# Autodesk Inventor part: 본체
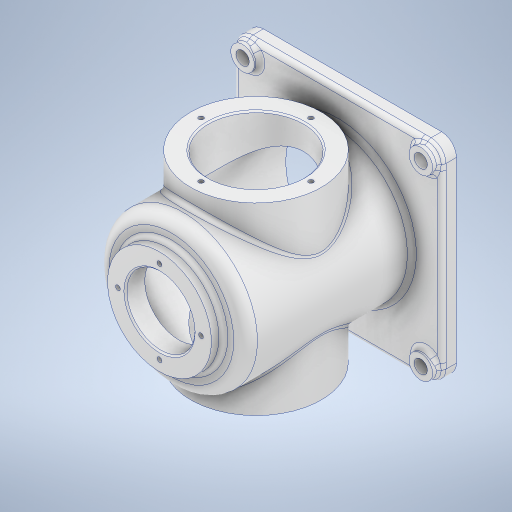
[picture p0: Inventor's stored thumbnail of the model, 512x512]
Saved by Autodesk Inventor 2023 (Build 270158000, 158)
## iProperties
Created: 2025-05
Part Number: 본체
Material: 알루미늄 6061
Document SubType Name: Modeling
Designer: user
Density: 2.7 g/cm^3
Appearance: 알루미늄 - 평지
Mass: 1130.9 g
Surface Area: 1201.4 cm^2
Volume: 418.852 cm^3
Author: user
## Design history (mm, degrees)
sketch "스케치3"
  geometry: C1 r 50 at (0, 0); 1 further point
  constraints: 1 centre point, 1 coincident
  dimensions: "d0" = 100 diameter of C1
extrude "돌출1" new body sketch "스케치3" distance "d1" = 122; taper "d2" = 0 deg
sketch "스케치9"
  geometry: L1 (-70, -70)-(70, -70); L2 (70, -70)-(70, 70); L3 (70, 70)-(-70, 70); L4 (-70, 70)-(-70, -70); L5 (-70, -70)-(70, 70); L6 (70, -70)-(-70, 70); 1 further point
  constraints: 12 end point, 2 midpoint, 2 parallel, 1 horizontal, 1 perpendicular
  dimensions: "d12" = 140 distance of L3.end L2.end; "d13" = 140 distance of L2.end L1.end
extrude "돌출4" join sketch "스케치9" distance "d14" = 10; taper "d15" = 0 deg
sketch "스케치12"
  geometry: L1 (-72.836, 65)-(75.341, 65); L2 (-70, 0)-(70, 0) reference; L3 (0, -24.4)-(0, 146.4) reference; C1 r 44 at (0, 65); 1 further point
  constraints: 2 end point, 2 point on line, 1 centre point, 1 horizontal
  dimensions: "d19" = 65 distance between parallel lines of L2 L1; "d20" = 88 diameter of C1
extrude "돌출6" join sketch "스케치12" stored distance "d21" = 124; taper "d22" = 0 deg
sketch "스케치10"
  geometry: C1 r 45 at (0, 0); 1 further point
  constraints: 1 centre point, 1 coincident
  dimensions: "d16" = 90 diameter of C1
extrude "돌출5" cut sketch "스케치10" distance "d17" = 117; taper "d18" = 0 deg
sketch "스케치13"
  geometry: L1 (0, 89.4)-(0, -81.4) reference; L2 (64.744, 0)-(-80.929, 0); L3 (-70, 65)-(70, 65) reference; C1 r 32 at (0, 0); 1 further point
  constraints: 2 end point, 2 point on line, 1 centre point, 1 horizontal
  dimensions: "d23" = 64 diameter of C1; "d24" = 65 distance between parallel lines of L3 L2
extrude "돌출7" cut sketch "스케치13" extent not by distance; stored distance "d25" = 0; taper "d26" = 0 deg
sketch "스케치15"
  geometry: C1 r 35 at (0, 0); 1 further point
  constraints: 1 centre point, 1 coincident
  dimensions: "d27" = 70 diameter of C1
extrude "돌출8" join sketch "스케치15" distance "d28" = 8; taper "d29" = 0 deg
sketch "스케치16"
  geometry: C1 r 23 at (0, 0); 1 further point
  constraints: 1 centre point, 1 coincident
  dimensions: "d30" = 46 diameter of C1
extrude "돌출9" cut sketch "스케치16" extent not by distance; stored distance "d31" = 0; taper "d32" = 0 deg
sketch "스케치17"
  geometry: L1 (-98, 0)-(98, 0) reference; L2 (0, -98)-(0, 98) reference; 2 further points
  constraints: 1 point on line
  dimensions: "d34" = 56 diameter of point (-28, 0) L2
hole "구멍1" sketch "스케치17" at (-28, 0) diameter "d35" = 3.242; stored, may be unused: countersink angle "d39" = 90 deg, drill point angle "d41" = 118 deg; dims "d36" = 8, "d37" = 4, "d38" = 2, "d40" = 10
sketch "스케치18"
  geometry: L1 (0, -91)-(0, 91) reference; L2 (-79.6, 0)-(91.263, 0); L3 (70, -65)-(-70, -65) reference; 2 further points
  constraints: 2 end point, 1 horizontal, 1 point on line
  dimensions: "d45" = 65 distance between parallel lines of L3 L2; "d46" = 74 diameter of point (0, 37) L2
hole "구멍2" sketch "스케치18" at (0, 37) diameter "d47" = 3.242; stored, may be unused: countersink angle "d51" = 90 deg, drill point angle "d53" = 118 deg; dims "d48" = 8, "d49" = 4, "d50" = 2, "d52" = 10
fillet "모깎기1" dims "d57" = 10
sketch "스케치19"
  geometry: C1 r 8 at (60, 60); C2 r 8 at (60, -60); C3 r 8 at (-60, 60); C4 r 8 at (-60, -60); A1 r 10 centre (60, 60) between (70, 60) and (60, 70) reference; A2 r 10 centre (60, -60) between (60, -70) and (70, -60) reference; A3 r 10 centre (-60, 60) between (-60, 70) and (-70, 60) reference; A4 r 10 centre (-60, -60) between (-70, -60) and (-60, -70) reference; 1 further point
  constraints: 4 centre point, 4 coincident
  dimensions: "d58" = 16 diameter of C1; "d59" = 16 diameter of C2; "d60" = 16 diameter of C3; "d61" = 16 diameter of C4
extrude "돌출10" join sketch "스케치19" distance "d62" = 4; taper "d63" = 0 deg
sketch "스케치20"
  geometry: 1 further point
sketch "스케치21"
  geometry: C1 r 8 at (0, -120) reference; C2 r 4.5 at (0, -120); C3 r 4.5 at (-120, -120); C4 r 8 at (-120, 0) reference; C5 r 4.5 at (-120, 0); C6 r 4.5 at (0, 0); A1 r 10 centre (-120, -120) between (-130, -120) and (-120, -130) reference; A2 r 10 centre (0, 0) between (10, 0) and (0, 10) reference; 1 further point
  constraints: 4 centre point, 4 coincident
  dimensions: "d65" = 9 diameter of C2; "d66" = 9 diameter of C3; "d67" = 9 diameter of C5; "d68" = 9 diameter of C6
extrude "돌출11" cut sketch "스케치21" extent not by distance; stored distance "d69" = 4; taper "d70" = 0 deg
node "작업 평면3"
sketch "스케치25" dims "d1" = 122, "d2" = 0
  geometry: L1 (0, -26)-(0, 156) reference; L2 (60, 0)-(-60, 0) reference; 2 further points
  constraints: 1 point on line, 1 other
  dimensions: "d77" = 80 distance from line of L2 point (0, 80)
feature "엠보싱2" sketch "스케치25" dims "d1" = 122, "d2" = 0, "d78" = 0.5, "d79" = 0
fillet "모깎기2" dims "d80" = 3
chamfer "모따기1" distance "d81" = 1; stored, may be unused: second distance "d82" = 2, angle "d83" = 45 deg
fillet "모깎기3" dims "d84" = 8
node "솔리드1"
pattern_circular "원형 패턴1" dims angle "d43" = 360 deg
pattern_circular "원형 패턴2" dims angle "d55" = 360 deg
mirror "미러1"
feature "A9D066F2-1C7D-4E18-AEED-F7BC21143FA4" dims "d35" = 3.242, "d36" = 8, "d37" = 4, "d38" = 2, "d39" = 90 deg, "d40" = 10, "d41" = 118 deg
other parameters: "d76" = -187.75
